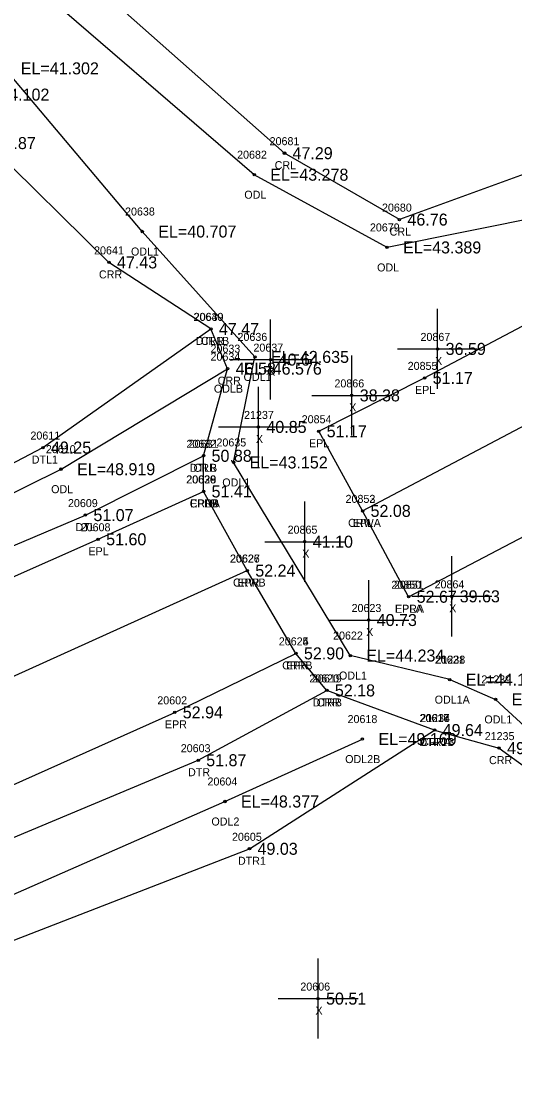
# Model space of a CAD drawing. Extents: x 2420351 to 2422725, y 845330 to 846558.
# Drawn here: x 2421716.5 to 2421778.1, y 845732.5 to 845866.8 of the extents above; entities that cross this region are included whole.
import ezdxf

# ---------------------------------------------------------------- set-up
doc = ezdxf.new("R2010")
doc.units = 0
for name, color, linetype in [('BR_GRID DOTS', 7, 'Continuous'), ('RD_DTM_BkLn1', 7, 'Continuous'), ('RD_EX_H2O', 7, 'Continuous'), ('RD_EX_H2O_txCode', 7, 'Continuous'), ('RD_EX_Misc', 7, 'Continuous'), ('RD_EX_Misc_txCode', 7, 'Continuous'), ('RD_EX_Road', 7, 'Continuous'), ('RD_EX_Road_txCode', 7, 'Continuous'), ('RD_EX_TX_H2O_ELEV', 7, 'Continuous'), ('RD_EX_TX_Misc_ELEV', 7, 'Continuous'), ('RD_EX_TX_Road_ELEV', 7, 'Continuous'), ('RD_HC_Survey_ELEV', 7, 'Continuous'), ('RD_HC_Survey_txCode', 7, 'Continuous'), ('RD_SMD_Locator', 7, 'Continuous')]:
    doc.layers.add(name, color=color, linetype=linetype)

msp = doc.modelspace()

# ---------------------------------------------------------------- linework, layer by layer
at = {"layer": 'BR_GRID DOTS'}
for p, q in [((2421759.07, 845805.68), (2421797.91, 845826.17)), ((2421764.83, 845794.95), (2421804.01, 845815.51))]:
    msp.add_line(p, q, dxfattribs=at)
msp.add_lwpolyline([(2421764.83, 845794.95), (2421759.07, 845805.68), (2421753.59, 845815.63), (2421766.83, 845822.3), (2421780.42, 845829.53), (2421792.55, 845836.37), (2421797.91, 845826.17), (2421804.01, 845815.51)], dxfattribs=at)
for centre in [(2421766.83, 845822.3), (2421753.59, 845815.63), (2421759.07, 845805.68), (2421759.07, 845805.68), (2421764.83, 845794.95), (2421764.83, 845794.95)]:
    msp.add_circle(centre, 0.15, dxfattribs=at)
at = {"layer": 'RD_DTM_BkLn1'}
msp.add_lwpolyline([(2420378.71, 845690.53), (2420439.5, 845704.09), (2420489.95, 845712.49), (2420551.89, 845719.42), (2420551.95, 845719.57), (2420607.12, 845722.67), (2420682.92, 845723.04), (2420749.65, 845719.68), (2420796.31, 845715.7), (2420900.74, 845705.33), (2421018.16, 845694.11), (2421114.61, 845684.8), (2421175.74, 845680.1), (2421234.97, 845678.35), (2421292.42, 845679.46), (2421350.56, 845683.65), (2421414.53, 845692.12), (2421472.54, 845703.63), (2421533.08, 845718.31), (2421555.4, 845725.02), (2421609.81, 845741.71), (2421666.58, 845762.88), (2421744.67, 845798.22)], dxfattribs=at)
at = {"layer": 'RD_EX_H2O'}
for points in [[(2420975.55, 846190.58), (2420976.37, 846105.11), (2420974.31, 845997.82), (2420976.03, 845896.74), (2420974.59, 845794.18), (2420975.37, 845743.63), (2420984.12, 845720.99), (2420999.91, 845711.18), (2421116.7, 845699.77), (2421177.35, 845696.01), (2421236.57, 845694.11), (2421292.07, 845694.75), (2421349.67, 845700.43), (2421411.57, 845706.56), (2421470.63, 845718.76), (2421529.96, 845732.93), (2421551.14, 845737.51), (2421602.97, 845753.33), (2421656.85, 845776.48), (2421724.45, 845805.15), (2421739.21, 845812.56)], [(2420980.17, 846190.47), (2420980.93, 846104.85), (2420980.02, 845997.99), (2420979.17, 845896.92), (2420978.72, 845794), (2420978.72, 845743.89), (2420987.58, 845724.3), (2421000.53, 845717.13), (2421117.24, 845704.33), (2421178.3, 845699.94), (2421237.1, 845697.97), (2421292.37, 845698.66), (2421349.43, 845702.84), (2421410.88, 845710.25), (2421469.94, 845721.7), (2421529.19, 845736.54), (2421550.26, 845742.27), (2421602, 845757.38), (2421655.89, 845778.44), (2421721.41, 845810.89), (2421742.22, 845823.45)], [(2421769.97, 845784.59), (2421757.53, 845787.6), (2421742.96, 845811.73), (2421745.62, 845824.92), (2421731.55, 845840.59), (2421714.37, 845860.98), (2421703.55, 845865.16), (2421670.27, 845895.91), (2421653.18, 845938.84), (2421661.84, 845966.62), (2421645.65, 846012.9), (2421638.29, 846027.24), (2421576.72, 846012.28), (2421545.4, 846011.31), (2421531.8, 846021.91), (2421540.87, 846056.88), (2421568.83, 846092.43), (2421605.18, 846118.43)], [(2421789.64, 845837.83), (2421782.25, 845842.65), (2421762.14, 845838.6), (2421745.54, 845847.69), (2421715.82, 845873.29), (2421690.16, 845897.6), (2421662.52, 845937.52), (2421691.81, 845952.74), (2421695.52, 845998.98), (2421690.3, 846033.46), (2421790.46, 846058.61), (2421873.55, 846071.45), (2421916.6, 846080.01)], [(2421803.88, 845842.86), (2421794.61, 845845.35), (2421789.35, 845845.31), (2421784.3, 845849.6), (2421763.68, 845842.08), (2421749.32, 845850.38), (2421719.73, 845876.64), (2421694.91, 845901.66), (2421677.7, 845939.02), (2421693.6, 845947.01), (2421705.85, 845990.03), (2421703.45, 845999.67)], [(2421739.21, 845808.11), (2421739.21, 845812.56), (2421742.22, 845823.45), (2421740.13, 845828.42), (2421727.39, 845836.73), (2421712.23, 845851.64)], [(2421348.44, 845711.4), (2421408.11, 845718.43), (2421468.58, 845729.77), (2421526.52, 845745.24), (2421541.81, 845745.64), (2421549.75, 845745.7), (2421570.45, 845751.87), (2421591.88, 845757.66), (2421599.3, 845765.73), (2421650.04, 845787.07), (2421668.02, 845786.79), (2421719.15, 845813.59), (2421740.13, 845828.42)], [(2421768.08, 845778.29), (2421754.61, 845783.24), (2421750.75, 845787.87)], [(2421769.97, 845784.59), (2421775.7, 845782.12), (2421786.73, 845771.94), (2421823.71, 845730.54), (2421836.28, 845679.34), (2421832.24, 845660.92), (2421820.77, 845638.45), (2421823.1, 845608.96), (2421831.71, 845583.35), (2421823.31, 845575.86), (2421811.92, 845548.94), (2421818.99, 845509.7), (2421790.81, 845485.52), (2421791.34, 845474.13), (2421803.96, 845452.08), (2421836.18, 845421.02), (2421870.76, 845406.66), (2421878.5, 845385.15), (2421867.47, 845378.72), (2421847.36, 845376.11), (2421845.3, 845344.22)], [(2421462.85, 845683.51), (2421560.11, 845709.79), (2421615.97, 845726.65), (2421668.49, 845745.18), (2421738.54, 845774.52), (2421754.61, 845783.24)], [(2421462.85, 845683.51), (2421463.34, 845677.36), (2421472.12, 845675.5), (2421563.69, 845698.26), (2421619.71, 845715.72), (2421671.24, 845734.85), (2421744.95, 845763.45), (2421768.08, 845778.29)], [(2421768.08, 845778.29), (2421776.13, 845776.03), (2421785.06, 845769.58), (2421818.61, 845726.06), (2421831.42, 845677.9), (2421825.05, 845663.86), (2421816.1, 845638.14), (2421820.64, 845608.52), (2421828.09, 845585.14), (2421817.9, 845575.21), (2421808.75, 845549.61), (2421816.7, 845511.81), (2421785.75, 845489.97), (2421789.04, 845473.23), (2421801.09, 845449.66), (2421834.75, 845418.44), (2421870.95, 845402.12), (2421876.24, 845387.07), (2421866.97, 845385.32), (2421844.91, 845376.57), (2421842.84, 845344.63)], [(2421465.82, 845681.42), (2421562.1, 845703.19), (2421618.04, 845721.04), (2421670.65, 845738.09), (2421741.88, 845769.36), (2421759.06, 845777.16)]]:
    msp.add_lwpolyline(points, dxfattribs=at)
at = {"layer": 'RD_EX_Misc'}
for p, q in [((2421768.45, 845820.92), (2421768.45, 845830.92)), ((2421747.59, 845819.58), (2421747.59, 845829.58)), ((2421763.45, 845825.92), (2421773.45, 845825.92)), ((2421742.59, 845824.58), (2421752.59, 845824.58)), ((2421757.72, 845815.11), (2421757.72, 845825.11)), ((2421746.06, 845811.17), (2421746.06, 845821.17)), ((2421752.72, 845820.11), (2421762.72, 845820.11)), ((2421741.06, 845816.17), (2421751.06, 845816.17)), ((2421751.85, 845796.83), (2421751.85, 845806.83)), ((2421746.85, 845801.83), (2421756.85, 845801.83)), ((2421770.21, 845790), (2421770.21, 845800)), ((2421759.84, 845787.04), (2421759.84, 845797.04)), ((2421765.21, 845795), (2421775.21, 845795)), ((2421754.84, 845792.04), (2421764.84, 845792.04)), ((2421753.51, 845739.73), (2421753.51, 845749.73)), ((2421748.51, 845744.73), (2421758.51, 845744.73))]:
    msp.add_line(p, q, dxfattribs=at)
at = {"layer": 'RD_EX_Road'}
for points in [[(2420388.28, 845680.39), (2420441.29, 845692.04), (2420492.62, 845700.7), (2420553.92, 845707.41), (2420607.69, 845710.85), (2420682.38, 845711.26), (2420749.44, 845707.27), (2420795.12, 845703.44), (2420900.28, 845693.42), (2421017.17, 845682.19), (2421113.9, 845672.97), (2421174.87, 845668.16), (2421234.59, 845666.13), (2421293, 845667.25), (2421351.24, 845671.5), (2421419.82, 845681.17), (2421463.19, 845688.63), (2421558.82, 845713.18), (2421614.57, 845730.45), (2421670.73, 845751.42), (2421735.61, 845780.5), (2421750.75, 845787.87), (2421744.67, 845798.22), (2421739.21, 845808.11)], [(2421350.22, 845695.49), (2421412.35, 845704.28), (2421471.12, 845715.7), (2421530.23, 845730.14), (2421551.47, 845736), (2421603.47, 845751.93), (2421659.09, 845772.43), (2421726.04, 845802.13), (2421739.21, 845808.11)]]:
    msp.add_lwpolyline(points, dxfattribs=at)
at = {"layer": 'RD_SMD_Locator'}
for centre in [(2421749.32, 845850.38), (2421745.54, 845847.69), (2421763.68, 845842.08), (2421731.55, 845840.59), (2421762.14, 845838.6), (2421727.39, 845836.73), (2421740.13, 845828.42), (2421740.13, 845828.42), (2421768.45, 845825.92), (2421745.62, 845824.92), (2421747.59, 845824.58), (2421742.22, 845823.45), (2421742.22, 845823.45), (2421757.72, 845820.11), (2421746.06, 845816.17), (2421719.15, 845813.59), (2421739.21, 845812.56), (2421739.21, 845812.56), (2421742.96, 845811.73), (2421721.41, 845810.89), (2421739.21, 845808.11), (2421739.21, 845808.11), (2421739.21, 845808.11), (2421724.45, 845805.15), (2421726.04, 845802.13), (2421751.85, 845801.83), (2421744.67, 845798.22), (2421744.67, 845798.22), (2421770.21, 845795), (2421759.84, 845792.04), (2421750.75, 845787.87), (2421750.75, 845787.87), (2421757.53, 845787.6), (2421769.97, 845784.59), (2421769.97, 845784.59), (2421754.61, 845783.24), (2421754.61, 845783.24), (2421775.7, 845782.12), (2421735.61, 845780.5), (2421768.08, 845778.29), (2421768.08, 845778.29), (2421768.08, 845778.29), (2421759.06, 845777.16), (2421776.13, 845776.03), (2421738.54, 845774.52), (2421741.88, 845769.36), (2421744.95, 845763.45), (2421753.51, 845744.73)]:
    msp.add_circle(centre, 0.15, dxfattribs=at)

# ---------------------------------------------------------------- texts
at = {"layer": 'RD_EX_H2O_txCode'}
for s, p in [('20681', (2421747.46, 845851.38)), ('20682', (2421743.4, 845849.69)), ('CRL', (2421748.09, 845848.38)), ('ODL', (2421744.3, 845844.69)), ('20638', (2421729.4, 845842.59)), ('20680', (2421761.5, 845843.08)), ('20679', (2421759.99, 845840.6)), ('CRL', (2421762.45, 845840.08)), ('20641', (2421725.53, 845837.73)), ('ODL1', (2421730.14, 845837.59)), ('CRR', (2421726.14, 845834.73)), ('ODL', (2421760.89, 845835.6)), ('20640', (2421737.95, 845829.42)), ('20639', (2421737.99, 845829.42)), ('DTL1B', (2421738.25, 845826.42)), ('CRR', (2421738.87, 845826.42)), ('20636', (2421743.45, 845826.92)), ('20633', (2421740.08, 845825.45)), ('20634', (2421740.08, 845824.45)), ('CRR', (2421740.97, 845821.45)), ('ODL1', (2421744.21, 845821.92)), ('ODLB', (2421740.5, 845820.45)), ('20611', (2421717.58, 845814.59)), ('20610', (2421719.51, 845812.89)), ('20632', (2421737.07, 845813.56)), ('20631', (2421737.35, 845813.56)), ('20635', (2421740.82, 845813.73)), ('DTL1', (2421717.74, 845811.59)), ('DTLB', (2421737.49, 845810.56)), ('CRR', (2421737.96, 845810.56)), ('20630', (2421737.03, 845809.11)), ('ODL', (2421720.17, 845807.89)), ('ODL1', (2421741.55, 845808.73)), ('20609', (2421722.27, 845806.15)), ('CRRA', (2421737.47, 845806.11)), ('DTL', (2421723.2, 845803.15)), ('20624', (2421748.61, 845788.87)), ('20622', (2421755.39, 845789.6)), ('20621', (2421768.11, 845786.59)), ('21238', (2421768.18, 845786.59)), ('CRRB', (2421749.03, 845785.87)), ('ODL1', (2421756.13, 845784.6)), ('20620', (2421752.42, 845784.24)), ('20619', (2421752.75, 845784.24)), ('21239', (2421773.91, 845784.12)), ('DTRB', (2421752.86, 845781.24)), ('CRR', (2421753.35, 845781.24)), ('ODL1A', (2421768.08, 845781.59)), ('ODL1A', (2421768.08, 845781.59)), ('20616', (2421766.19, 845779.29)), ('20617', (2421766.22, 845779.29)), ('21234', (2421766.28, 845779.29)), ('20618', (2421757.2, 845779.16)), ('ODL1', (2421774.29, 845779.12)), ('21235', (2421774.33, 845777.03)), ('20603', (2421736.36, 845775.52)), ('DTR1B', (2421766.17, 845776.29)), ('CRRA', (2421766.34, 845776.29)), ('CRRA', (2421766.34, 845776.29)), ('ODL2B', (2421756.9, 845774.16)), ('CRR', (2421774.87, 845774.03)), ('DTR', (2421737.27, 845772.52)), ('20604', (2421739.7, 845771.36)), ('ODL2', (2421740.19, 845766.36)), ('20605', (2421742.76, 845764.45)), ('DTR1', (2421743.51, 845761.45))]:
    msp.add_text(s, height=1, dxfattribs=at).set_placement(p)
at = {"layer": 'RD_EX_Misc_txCode'}
for s, p in [('20867', (2421766.31, 845826.92)), ('20637', (2421745.44, 845825.58)), ('X', (2421768.13, 845823.92)), ('X', (2421747.27, 845822.58)), ('20866', (2421755.56, 845821.11)), ('21237', (2421744.27, 845817.17)), ('X', (2421757.41, 845818.11)), ('X', (2421745.75, 845814.17)), ('20865', (2421749.71, 845802.83)), ('X', (2421751.54, 845799.83)), ('20864', (2421768.07, 845796)), ('20623', (2421757.7, 845793.04)), ('X', (2421769.9, 845793)), ('X', (2421759.52, 845790.04)), ('20606', (2421751.3, 845745.73)), ('X', (2421753.19, 845742.73))]:
    msp.add_text(s, height=1, dxfattribs=at).set_placement(p)
at = {"layer": 'RD_EX_Road_txCode'}
for s, p in [('20855', (2421764.71, 845823.3)), ('EPL', (2421765.62, 845820.3)), ('20854', (2421751.47, 845816.63)), ('EPL', (2421752.38, 845813.63)), ('20628', (2421737.07, 845809.11)), ('20629', (2421737.07, 845809.11)), ('EPRB', (2421737.51, 845806.11)), ('EPLB', (2421737.54, 845806.11)), ('20852', (2421756.95, 845806.68)), ('EPL', (2421757.86, 845803.68)), ('20608', (2421723.86, 845803.13)), ('EPL', (2421724.83, 845800.13)), ('20627', (2421742.53, 845799.22)), ('EPR', (2421743.44, 845796.22)), ('20850', (2421762.67, 845795.95)), ('20851', (2421762.99, 845795.95)), ('EPRA', (2421763.11, 845792.95)), ('EPLA', (2421763.13, 845792.95)), ('20625', (2421748.61, 845788.87)), ('EPR', (2421749.52, 845785.87)), ('20602', (2421733.43, 845781.5)), ('EPR', (2421734.38, 845778.5))]:
    msp.add_text(s, height=1, dxfattribs=at).set_placement(p)
at = {"layer": 'RD_EX_TX_H2O_ELEV'}
for s, p in [('EL=41.302', (2421716.37, 845860.23)), ('EL=44.102', (2421710.19, 845856.95)), ('46.87', (2421713.23, 845850.89)), ('46.87', (2421713.23, 845850.89)), ('47.29', (2421750.32, 845849.63)), ('EL=43.278', (2421747.54, 845846.94)), ('46.76', (2421764.68, 845841.33)), ('EL=40.707', (2421733.55, 845839.84)), ('EL=43.389', (2421764.14, 845837.85)), ('47.43', (2421728.39, 845835.98)), ('47.47', (2421741.13, 845827.67)), ('47.47', (2421741.13, 845827.67)), ('EL=42.635', (2421747.62, 845824.17)), ('46.58', (2421743.22, 845822.7)), ('EL=46.576', (2421744.22, 845822.7)), ('49.25', (2421720.15, 845812.84)), ('50.88', (2421740.21, 845811.81)), ('50.88', (2421740.21, 845811.81)), ('EL=43.152', (2421744.96, 845810.98)), ('EL=48.919', (2421723.41, 845810.14)), ('51.41', (2421740.21, 845807.36)), ('51.07', (2421725.45, 845804.4)), ('52.90', (2421751.75, 845787.12)), ('EL=44.234', (2421759.53, 845786.85)), ('EL=44.103', (2421771.97, 845783.84)), ('EL=44.103', (2421771.97, 845783.84)), ('52.18', (2421755.61, 845782.49)), ('52.18', (2421755.61, 845782.49)), ('EL=44.754', (2421777.7, 845781.37)), ('49.64', (2421769.08, 845777.54)), ('49.64', (2421769.08, 845777.54)), ('49.64', (2421769.08, 845777.54)), ('EL=49.169', (2421761.06, 845776.41)), ('49.07', (2421777.13, 845775.28)), ('51.87', (2421739.54, 845773.77)), ('EL=48.377', (2421743.88, 845768.61)), ('49.03', (2421745.95, 845762.7))]:
    msp.add_text(s, height=1.5, dxfattribs=at).set_placement(p)
at = {"layer": 'RD_EX_TX_Misc_ELEV'}
for s, p in [('36.59', (2421769.45, 845825.17)), ('40.64', (2421748.59, 845823.83)), ('38.38', (2421758.72, 845819.36)), ('40.85', (2421747.06, 845815.42)), ('41.10', (2421752.85, 845801.08)), ('39.63', (2421771.21, 845794.25)), ('40.73', (2421760.84, 845791.29)), ('50.51', (2421754.51, 845743.98))]:
    msp.add_text(s, height=1.5, dxfattribs=at).set_placement(p)
at = {"layer": 'RD_EX_TX_Road_ELEV'}
for s, p in [('51.17', (2421767.83, 845821.55)), ('51.17', (2421754.59, 845814.88)), ('51.41', (2421740.21, 845807.36)), ('51.41', (2421740.21, 845807.36)), ('52.08', (2421760.07, 845804.93)), ('51.60', (2421727.04, 845801.38)), ('52.24', (2421745.67, 845797.47)), ('52.67', (2421765.83, 845794.2)), ('52.67', (2421765.83, 845794.2)), ('52.90', (2421751.75, 845787.12)), ('52.94', (2421736.61, 845779.75))]:
    msp.add_text(s, height=1.5, dxfattribs=at).set_placement(p)
at = {"layer": 'RD_HC_Survey_ELEV'}
for s, p in [('52.08', (2421760.07, 845804.93)), ('52.24', (2421745.67, 845797.47))]:
    msp.add_text(s, height=1.5, dxfattribs=at).set_placement(p)
at = {"layer": 'RD_HC_Survey_txCode'}
for s, p in [('20853', (2421756.95, 845806.68)), ('CRWA', (2421757.27, 845803.68)), ('20626', (2421742.5, 845799.22)), ('CRWB', (2421742.88, 845796.22))]:
    msp.add_text(s, height=1, dxfattribs=at).set_placement(p)

doc.saveas('drawing.dxf')
